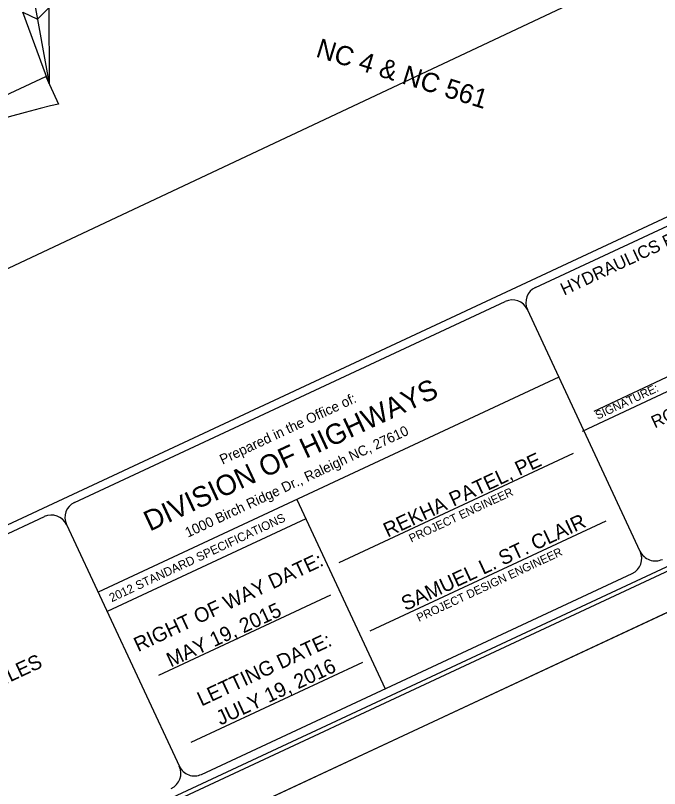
# Model space of a CAD drawing. Extents: x 2318983 to 2324558, y 920396 to 924651.
# Drawn here: x 2322471 to 2323397, y 921581 to 922694 of the extents above; entities that cross this region are included whole.
import ezdxf

# ---------------------------------------------------------------- set-up
doc = ezdxf.new("R2010")
doc.units = 0
for name, color, linetype in [('Prop Dimension', 7, 'Continuous'), ('Prop DSN Text', 7, 'Continuous'), ('Prop Shade Light', 7, 'Continuous'), ('Prop Terminator CELL', 7, 'Continuous'), ('Sheet Cutting Line CELL', 7, 'Continuous'), ('Sheet Data Field CELL', 7, 'Continuous'), ('Sheet Plot Border Inside CELL', 7, 'Continuous'), ('Sheet Plot Border Outside CELL', 7, 'Continuous'), ('Sheet Title CELL', 7, 'Continuous')]:
    doc.layers.add(name, color=color, linetype=linetype)

msp = doc.modelspace()

# ---------------------------------------------------------------- linework, layer by layer
at = {"layer": 'Prop Dimension'}
msp.add_line((2323496.8, 922818), (2322321.6, 922264.7), dxfattribs=at)
at = {"layer": 'Prop DSN Text'}
msp.add_line((2322482.6, 922798.7), (2322519.1, 922595.5), dxfattribs=at)
at = {"layer": 'Prop Shade Light'}
msp.add_lwpolyline([(2321795.7, 922244.4), (2321785.6, 922266.1), (2321799.3, 922272.5), (2322514, 922606.4), (2322532.6, 922566.6), (2322520.8, 922563.9), (2322506.2, 922560.4), (2322484.7, 922554.6), (2322461.3, 922548), (2322451.7, 922545.1), (2322448.3, 922544.1), (2322446, 922543.4), (2322439.7, 922541.4), (2322439.7, 922541.4), (2322439.7, 922541.4), (2322392.8, 922523.2), (2321809.5, 922250.8)], close=True, dxfattribs=at)
at = {"layer": 'Prop Terminator CELL'}
msp.add_lwpolyline([(2322518.3, 922705.1), (2322519.1, 922595.5), (2322481, 922699), (2322502.3, 922688.8)], close=True, dxfattribs=at)
at = {"layer": 'Sheet Cutting Line CELL'}
msp.add_line((2320654.8, 920549.7), (2324317.2, 922258.9), dxfattribs=at)
at = {"layer": 'Sheet Plot Border Inside CELL'}
msp.add_lwpolyline([(2320660.3, 920611.7), (2324284.6, 922303.2), (2323213.7, 924597.8), (2319589.4, 922906.3)], close=True, dxfattribs=at)
at = {"layer": 'Sheet Plot Border Outside CELL'}
msp.add_lwpolyline([(2323200.7, 924651.2), (2319538.3, 922942), (2320654.8, 920549.7), (2324317.2, 922258.9)], close=True, dxfattribs=at)
at = {"layer": 'Sheet Title CELL'}
for p, q in [((2320941.1, 921252.8), (2324029.4, 922694)), ((2323218.9, 922302.6), (2323653.3, 922505.3)), ((2323286.5, 922095.8), (2323766.4, 922319.8)), ((2322555.6, 921993), (2323175.4, 922282.3)), ((2323369.7, 921922.7), (2323207.3, 922270.6)), ((2323303.2, 922124.7), (2323616.9, 922271.2)), ((2323252.7, 922173.3), (2322589.4, 921863.8)), ((2322936.2, 921906.4), (2323273.6, 922063.9)), ((2322875.5, 921997.3), (2323002.6, 921724.9)), ((2321685.7, 921587), (2322512.1, 921972.7)), ((2322888.4, 921969.5), (2322602.3, 921836)), ((2322981.1, 921808.2), (2323320.9, 921966.8)), ((2322544, 921961.1), (2322706.4, 921613.1)), ((2322806, 921931.1), (2322806, 921931.1)), ((2322923.9, 921859.4), (2322676.6, 921743.9)), ((2322800.2, 921801.6), (2322800.2, 921801.6)), ((2322970.1, 921762.8), (2322722.7, 921647.3))]:
    msp.add_line(p, q, dxfattribs=at)
for points in [[(2321014.4, 920783.7), (2324233.1, 922285.9)], [(2322738.3, 921601.5), (2323358.1, 921890.8)]]:
    msp.add_lwpolyline(points, dxfattribs=at)
for centre, start, end in [((2323229, 922280.9), 115.0187, 205.0187), ((2323185.5, 922260.6), 25.0187, 115.0187), ((2322565.7, 921971.3), 115.0187, 205.0187), ((2322522.2, 921951), 25.0187, 115.0187), ((2323347.9, 921912.6), 295.0187, 25.0187), ((2323391.4, 921932.9), 205.0187, 295.0187), ((2322684.6, 921603.1), 295.0187, 25.0187), ((2322728.1, 921623.4), 205.0187, 295.0187)]:
    msp.add_arc(centre, 24, start, end, dxfattribs=at)

# ---------------------------------------------------------------- texts
at = {"layer": 'Prop DSN Text'}
msp.add_text('NC 4 & NC 561 ', height=27.683, rotation=342.6995, dxfattribs=at).set_placement((2322901.4, 922635.2))
at = {"layer": 'Sheet Data Field CELL'}
for s, p in [('REKHA PATEL, PE', (2323006.1, 921942.5)), ('SAMUEL L. ST. CLAIR', (2323031.9, 921836.6)), ('  MAY 19, 2015   ', (2322679.9, 921748.9)), ('LENGTH STRUCTURE TIP PROJECT B-4761 = 0.040 MILES ', (2321806.1, 921427.7)), ('JULY 19, 2016', (2322765.5, 921671.8))]:
    msp.add_text(s, height=21, rotation=25.0187, dxfattribs=at).set_placement(p)
at = {"layer": 'Sheet Title CELL'}
for s, height, p in [(' HYDRAULICS ENGINEER', 18, (2323254.1, 922287.8)), ('ROADWAY DESIGN', 17.999, (2323390.7, 922099.5)), ('DIVISION OF HIGHWAYS', 29.249, (2322663.9, 921951)), ('SIGNATURE:', 12, (2323308.4, 922112.1)), ('Prepared in the Office of:', 14.399, (2322768.5, 922047.4)), ('1000 Birch Ridge Dr., Raleigh NC, 27610', 14.4, (2322718.7, 921942.3)), ('PROJECT ENGINEER', 11.999, (2323040.2, 921935.1)), ('2012 STANDARD SPECIFICATIONS', 12.48, (2322609, 921849.3)), ('RIGHT OF WAY DATE: ', 21, (2322647, 921777.5)), ('PROJECT DESIGN ENGINEER', 11.999, (2323051.2, 921820.9)), ('LETTING DATE:', 21, (2322738.2, 921699.2))]:
    msp.add_text(s, height=height, rotation=25.0187, dxfattribs=at).set_placement(p)

doc.saveas('drawing.dxf')
